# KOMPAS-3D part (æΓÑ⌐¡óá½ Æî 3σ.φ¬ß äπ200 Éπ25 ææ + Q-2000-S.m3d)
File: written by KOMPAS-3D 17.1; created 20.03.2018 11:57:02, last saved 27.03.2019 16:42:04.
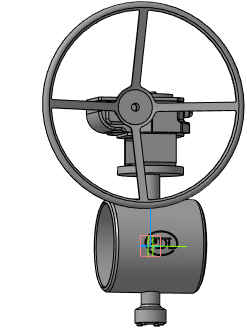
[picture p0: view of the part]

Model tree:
1. Операция без истории:5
